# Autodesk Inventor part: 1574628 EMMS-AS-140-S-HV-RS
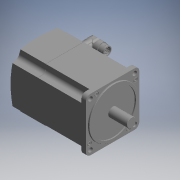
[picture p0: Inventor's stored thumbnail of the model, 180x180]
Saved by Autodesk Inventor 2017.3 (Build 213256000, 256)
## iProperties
Part Number: 1574628 EMMS-AS-140-S-HV-RS
Material: Generic
Catalog Web Link: www.cadenas.de
Description: EMMS-AS-servo motor
Vendor: FESTO
Document SubType Name: Modeling
Designer: partserver
Manufacturer: FESTO
Mass: 9600 g
Surface Area: 1690.04 cm^2
Volume: 3761.7 cm^3
Density: 1 g/cm^3
Appearance: PSOLRGB-175-175-175
Category: PARTsolutions
Company: FESTO
Title: 1574628 EMMS-AS-140-S-HV-RS
Author: Cadenas PARTsolutions
Comments: servo motor
PSOL_IDENT_0: {$CADENAS_DATA\23d-libs\festo\parts\e\emms\emms_as.prj},197 {VTYP=3D},{NB=1574628 EMMS-AS-140-S-HV-R
PSOL_IDENT_1: S},{LINA=1574628 EMMS-AS-140-S-HV-RS},{NN=EMMS-AS},{DATE=30.10.2020 09:47:04},{GEOMDATE=30.10.2020 0
PSOL_IDENT_2: 9:44:16},{VERSION=},{LINEID=5440},{WBVAR=},{WBNUMERIC=}  {NB=1574628 EMMS-AS-140-S-HV-RS},{LINA=1574
PSOL_IDENT_3: 628 EMMS-AS-140-S-HV-RS},{KT=DUMMY},{TNR=1574628},{TYP=EMMS-AS-140-S-HV-RS},{INFO=},{B1=140.500},{B2=
PSOL_IDENT_4: 141.700},{CNSMASSEXACT=9.6000},{VER=9},{VERS=29},{A=209.000},{AA=209},{DP=0},{L=0.0},{L1=0.0},{L2=0.
PSOL_IDENT_5: 0},{L3=0.0},{L4=0.0},{L5=0},{L6=0.0},{L7=0.0},{L8=0.00},{H=0},{H1=0},{H2=0},{D1=0.0},{D2=0.00},{D3=0
PSOL_IDENT_6: .00},{D4=0.0},{D5=0.0},{M=0},{MA=0.000},{M1=0},{M1A=0.000},{EOLDATE=}
NB: 1574628 EMMS-AS-140-S-HV-RS
NN: EMMS-AS
NT: servo motor
NBSYN: $TNR. $TYP.
LINA: 1574628 EMMS-AS-140-S-HV-RS
CATALOG: Festo
TNR: 1574628
TYP: EMMS-AS-140-S-HV-RS
CNSMASSEXACT: 9.6
A: 209
L3: 0
SUPPLIER: FESTO
ARTICLENO: 1574628 EMMS-AS-140-S-HV-RS
BOMINFO: 1574628 EMMS-AS-140-S-HV-RS
CREATOR: CADENAS GmbH
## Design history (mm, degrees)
sketch "Sketch_1"
  geometry: L1 (41, 250)-(41, -250); L2 (-109, -200)-(-109, 200); A1 r 250 centre (41, 0) between (-109, 200) and (-109, -200)
  constraints: 4 end point, 2 point on circle, 1 centre point
revolve "Revolution1" sketch "Sketch_1" stored, may be unused: angle "d0" = 70 deg
sketch "Sketch_2"
  geometry: L1 (-72.5, 72.5)-(-72.5, -72.5); L2 (-72.5, -72.5)-(72.5, -72.5); L3 (72.5, -72.5)-(72.5, 72.5); L4 (72.5, 72.5)-(-72.5, 72.5)
  constraints: 8 end point
extrude "Extrusion1" join sketch "Sketch_2" distance "d1" = 172.4; taper "d2" = 0 deg
sketch "Sketch_9"
  geometry: L1 (-255, -255)-(255, -255); L2 (255, -255)-(255, 255); L3 (255, 255)-(-255, 255); L4 (-255, 255)-(-255, -255); L5 (-70.25, -70.25)-(70.25, -70.25); L6 (70.25, -70.25)-(70.25, 70.25); L7 (70.25, 70.25)-(-70.25, 70.25); L8 (-70.25, 70.25)-(-70.25, -70.25)
  constraints: 16 end point
extrude "Extrusion2" cut sketch "Sketch_9" distance "d3" = 196.8; taper "d4" = 0 deg
sketch "Sketch_6"
  geometry: L1 (-80, -80)-(80, -80); L2 (80, -80)-(80, 80); L3 (80, 80)-(-80, 80); L4 (-80, 80)-(-80, -80); L5 (-78, -49.25)-(-58.25, -49.25); L6 (-49.25, -58.25)-(-49.25, -78); L7 (-49.25, -78)-(49.25, -78); L8 (49.25, -78)-(49.25, -58.25); L9 (58.25, -49.25)-(78, -49.25); L10 (78, -49.25)-(78, 49.25); L11 (78, 49.25)-(58.25, 49.25); L12 (49.25, 58.25)-(49.25, 78); L13 (49.25, 78)-(-49.25, 78); L14 (-49.25, 78)-(-49.25, 58.25); L15 (-58.25, 49.25)-(-78, 49.25); L16 (-78, 49.25)-(-78, -49.25); A1 r 9 centre (-58.25, -58.25) between (-49.25, -58.25) and (-58.25, -49.25); A2 r 9 centre (58.25, -58.25) between (58.25, -49.25) and (49.25, -58.25); A3 r 9 centre (58.25, 58.25) between (49.25, 58.25) and (58.25, 49.25); A4 r 9 centre (-58.25, 58.25) between (-58.25, 49.25) and (-49.25, 58.25)
  constraints: 32 end point, 8 point on circle, 4 centre point
extrude "Extrusion3" cut sketch "Sketch_6" distance "d5" = 199.2; taper "d6" = 0 deg
sketch "Sketch_3"
  geometry: L1 (-80, 80)-(-80, -80); L2 (-80, -80)-(80, -80); L3 (80, -80)-(80, 80); L4 (80, 80)-(-80, 80); L5 (-70.25, 58.25)-(-70.25, -58.25); L6 (-58.25, -70.25)-(58.25, -70.25); L7 (70.25, -58.25)-(70.25, 58.25); L8 (58.25, 70.25)-(-58.25, 70.25); A1 r 12 centre (-58.25, 58.25) between (-58.25, 70.25) and (-70.25, 58.25); A2 r 12 centre (-58.25, -58.25) between (-70.25, -58.25) and (-58.25, -70.25); A3 r 12 centre (58.25, -58.25) between (58.25, -70.25) and (70.25, -58.25); A4 r 12 centre (58.25, 58.25) between (70.25, 58.25) and (58.25, 70.25)
  constraints: 16 end point, 8 point on circle, 4 centre point
extrude "Extrusion4" cut sketch "Sketch_3" distance "d7" = 12.2; taper "d8" = 0 deg
sketch "Sketch_4"
  geometry: L1 (-70.85, 49.85)-(-70.85, -49.85); L2 (-70.85, -49.85)-(-58.85, -49.85); L3 (-49.85, -58.85)-(-49.85, -70.85); L4 (-49.85, -70.85)-(49.85, -70.85); L5 (49.85, -70.85)-(49.85, -58.85); L6 (58.85, -49.85)-(70.85, -49.85); L7 (70.85, -49.85)-(70.85, 49.85); L8 (70.85, 49.85)-(58.85, 49.85); L9 (49.85, 58.85)-(49.85, 70.85); L10 (49.85, 70.85)-(-49.85, 70.85); L11 (-49.85, 70.85)-(-49.85, 58.85); L12 (-58.85, 49.85)-(-70.85, 49.85); A1 r 9 centre (-58.85, -58.85) between (-49.85, -58.85) and (-58.85, -49.85); A2 r 9 centre (58.85, -58.85) between (58.85, -49.85) and (49.85, -58.85); A3 r 9 centre (58.85, 58.85) between (49.85, 58.85) and (58.85, 49.85); A4 r 9 centre (-58.85, 58.85) between (-58.85, 49.85) and (-49.85, 58.85)
  constraints: 24 end point, 8 point on circle, 4 centre point
extrude "Extrusion5" join sketch "Sketch_4" distance "d9" = 45.6; taper "d10" = 0 deg
sketch "Sketch7"
  geometry: 1 further point
hole "Hole1" sketch "Sketch7" at (58.336, 58.336) diameter "d11" = 11.3; stored, may be unused: countersink angle "d15" = 90 deg, drill point angle "d17" = 0 deg; dims "d12" = 6, "d13" = 4, "d14" = 2, "d16" = 12.2
pattern_linear "Rectangular Pattern1" dims "d20" = 116.67262, "d23" = 116.67262
sketch "Sketch_13"
  geometry: L1 (0, 0)-(-50, 0); L2 (-50, 0)-(-50, 11.5); L3 (-50, 11.5)-(-49.5, 12); L4 (-49.5, 12)-(-0.5, 12); L5 (-0.5, 12)-(-0.5, 58); L6 (-0.5, 58)-(-3.5, 58); L7 (-3.5, 58)-(-3.5, 64.5); L8 (-3.5, 64.5)-(-3, 65); L9 (-3, 65)-(0, 65); L10 (0, 65)-(0, 0); L11 (0, 0)-(-50, 0)
  constraints: 22 end point
revolve "Revolution2" sketch "Sketch_13" stored, may be unused: angle "d24" = 360 deg
sketch "Sketch_8"
  geometry: L1 (6, 61)-(-1, 61); L2 (-1, 61)-(-1, 66.5); L3 (-1, 66.5)-(6, 66.5); L4 (6, 66.5)-(6, 66); L5 (6, 66)-(0.6, 66); L6 (0, 65.4)-(0, 61); L7 (0, 61)-(-1, 61); A1 r 0.6 centre (0.6, 65.4) between (0.6, 66) and (0, 65.4)
  constraints: 14 end point, 2 point on circle, 1 centre point
revolve "Revolution3" sketch "Sketch_8" stored, may be unused: angle "d25" = 360 deg
pattern_linear "Rectangular Pattern2" dims "d28" = 105.14038, "d31" = 105.14038
sketch "Sketch_18"
  geometry: L1 (59.557, -40)-(58.113, -42.5); L2 (58.113, -42.5)-(59.557, -45); L3 (59.557, -45)-(62.443, -45); L4 (62.443, -45)-(63.887, -42.5); L5 (63.887, -42.5)-(62.443, -40); L6 (62.443, -40)-(59.557, -40)
  constraints: 12 end point
extrude "Extrusion6" cut sketch "Sketch_18" distance "d32" = 3; taper "d33" = 0 deg
pattern_linear "Rectangular Pattern3" dims "d36" = 105.14038, "d39" = 105.14038
sketch "Sketch_11"
  geometry: L1 (200.5, -61)-(180.5, -61); L2 (180.5, -61)-(180.5, -56.25); L3 (180.5, -56.25)-(200.5, -56.25); L4 (200.5, -56.25)-(200.5, -61); L5 (200.5, -61)-(180.5, -61)
  constraints: 10 end point
revolve "Revolution4" sketch "Sketch_11" stored, may be unused: angle "d40" = 360 deg
sketch "Sketch_50"
  geometry: L1 (200.5, 61)-(180.5, 61); L2 (180.5, 61)-(180.5, 65.75); L3 (180.5, 65.75)-(200.5, 65.75); L4 (200.5, 65.75)-(200.5, 61); L5 (200.5, 61)-(180.5, 61)
  constraints: 10 end point
revolve "Revolution5" sketch "Sketch_50" stored, may be unused: angle "d41" = 360 deg
sketch "Sketch_10"
  geometry: L1 (200.5, 61)-(180.5, 61); L2 (180.5, 61)-(180.5, 65.75); L3 (180.5, 65.75)-(200.5, 65.75); L4 (200.5, 65.75)-(200.5, 61); L5 (200.5, 61)-(180.5, 61)
  constraints: 10 end point
revolve "Revolution6" sketch "Sketch_10" stored, may be unused: angle "d42" = 360 deg
sketch "Sketch_51"
  geometry: L1 (200.5, -61)-(180.5, -61); L2 (180.5, -61)-(180.5, -56.25); L3 (180.5, -56.25)-(200.5, -56.25); L4 (200.5, -56.25)-(200.5, -61); L5 (200.5, -61)-(180.5, -61)
  constraints: 10 end point
revolve "Revolution7" sketch "Sketch_51" stored, may be unused: angle "d43" = 360 deg
sketch "Sketch_12"
  geometry: L1 (195.5, -61)-(180.5, -61); L2 (180.5, -61)-(180.5, -56.75); L3 (180.5, -56.75)-(195.25, -56.75); L4 (195.5, -57)-(195.5, -61); L5 (195.5, -61)-(180.5, -61); A1 r 0.25 centre (195.25, -57) between (195.5, -57) and (195.25, -56.75)
  constraints: 10 end point, 2 point on circle, 1 centre point
revolve "Revolution8" sketch "Sketch_12" stored, may be unused: angle "d44" = 360 deg
sketch "Sketch_14"
  geometry: L1 (195.5, 61)-(175.5, 61); L2 (175.5, 61)-(175.5, 65.25); L3 (175.5, 65.25)-(195.5, 65.25); L4 (195.5, 65.25)-(195.5, 61); L5 (195.5, 61)-(175.5, 61)
  constraints: 10 end point
revolve "Revolution9" sketch "Sketch_14" stored, may be unused: angle "d45" = 360 deg
sketch "Sketch_54"
  geometry: L1 (195.5, 61)-(175.5, 61); L2 (175.5, 61)-(175.5, 65.25); L3 (175.5, 65.25)-(195.5, 65.25); L4 (195.5, 65.25)-(195.5, 61); L5 (195.5, 61)-(175.5, 61)
  constraints: 10 end point
revolve "Revolution10" sketch "Sketch_54" stored, may be unused: angle "d46" = 360 deg
sketch "Sketch_55"
  geometry: L1 (195.5, -61)-(175.5, -61); L2 (175.5, -61)-(175.5, -56.75); L3 (175.5, -56.75)-(195.5, -56.75); L4 (195.5, -56.75)-(195.5, -61); L5 (195.5, -61)-(175.5, -61)
  constraints: 10 end point
revolve "Revolution11" sketch "Sketch_55" stored, may be unused: angle "d47" = 360 deg
sketch "Sketch_15"
  geometry: L1 (-63, 41.345)-(-61, 40.191); L2 (-61, 40.191)-(-59, 41.345); L3 (-59, 41.345)-(-59, 43.655); L4 (-59, 43.655)-(-61, 44.809); L5 (-61, 44.809)-(-63, 43.655); L6 (-63, 43.655)-(-63, 41.345)
  constraints: 12 end point
extrude "Extrusion7" cut sketch "Sketch_15" distance "d48" = 12; taper "d49" = 0 deg
sketch "Sketch_21"
  geometry: L1 (40.5, 59.845)-(42.5, 58.691); L2 (42.5, 58.691)-(44.5, 59.845); L3 (44.5, 59.845)-(44.5, 62.155); L4 (44.5, 62.155)-(42.5, 63.309); L5 (42.5, 63.309)-(40.5, 62.155); L6 (40.5, 62.155)-(40.5, 59.845)
  constraints: 12 end point
extrude "Extrusion8" cut sketch "Sketch_21" distance "d50" = 12; taper "d51" = 0 deg
sketch "Sketch_52"
  geometry: L1 (59, -43.655)-(61, -44.809); L2 (61, -44.809)-(63, -43.655); L3 (63, -43.655)-(63, -41.345); L4 (63, -41.345)-(61, -40.191); L5 (61, -40.191)-(59, -41.345); L6 (59, -41.345)-(59, -43.655)
  constraints: 12 end point
extrude "Extrusion9" cut sketch "Sketch_52" distance "d52" = 12; taper "d53" = 0 deg
sketch "Sketch_53"
  geometry: L1 (-44.5, -62.155)-(-42.5, -63.309); L2 (-42.5, -63.309)-(-40.5, -62.155); L3 (-40.5, -62.155)-(-40.5, -59.845); L4 (-40.5, -59.845)-(-42.5, -58.691); L5 (-42.5, -58.691)-(-44.5, -59.845); L6 (-44.5, -59.845)-(-44.5, -62.155)
  constraints: 12 end point
extrude "Extrusion10" cut sketch "Sketch_53" distance "d54" = 12; taper "d55" = 0 deg
sketch "Sketch_16"
  geometry: L1 (137.9, -22)-(137.9, -45); L2 (137.9, -45)-(138.9, -46); L3 (138.9, -46)-(161.9, -46); L4 (161.9, -46)-(162.9, -45); L5 (162.9, -45)-(162.9, -22); L6 (162.9, -22)-(161.9, -21); L7 (161.9, -21)-(138.9, -21); L8 (138.9, -21)-(137.9, -22)
  constraints: 16 end point
extrude "Extrusion11" join sketch "Sketch_16" distance "d56" = 2.45; taper "d57" = 0 deg
sketch "Sketch_20"
  geometry: L1 (-23.6, 75.65)-(-23.6, 73.3); L2 (-23.6, 73.3)-(-25.85, 73.3); L3 (-25.85, 73.3)-(-25.85, 75.35); L4 (-25.85, 75.35)-(-25.55, 75.65); L5 (-25.55, 75.65)-(-23.6, 75.65); L6 (-23.6, 75.65)-(-23.6, 73.3)
  constraints: 12 end point
revolve "Revolution12" sketch "Sketch_20" stored, may be unused: angle "d58" = 360 deg
pattern_linear "Rectangular Pattern4" dims "d61" = 19.8, "d64" = 19.8
sketch "Sketch_23"
  geometry: L1 (150.4, 94.2)-(150.4, 73.3); L2 (150.4, 73.3)-(143.4, 73.3); L3 (143.4, 73.3)-(143.4, 82.757); L4 (143.4, 82.757)-(143.843, 83.2); L5 (143.843, 83.2)-(145.05, 83.2); L6 (145.05, 83.2)-(145.05, 84.05); L7 (145.05, 84.05)-(144.4, 84.7); L8 (144.4, 84.7)-(144.4, 92.74); L9 (144.4, 92.74)-(144.86, 93.2); L10 (144.86, 93.2)-(145.05, 93.2); L11 (145.05, 93.2)-(145.05, 94.2); L12 (145.05, 94.2)-(150.4, 94.2); L13 (150.4, 94.2)-(150.4, 73.3)
  constraints: 26 end point
revolve "Revolution13" sketch "Sketch_23" stored, may be unused: angle "d65" = 360 deg
thread "Thread1" dims "d66" = 8.04, "d67" = 0
sketch "Sketch_24"
  geometry: L1 (139.5, -24.177)-(140.5, -24.755); L2 (140.5, -24.755)-(141.5, -24.177); L3 (141.5, -24.177)-(141.5, -23.023); L4 (141.5, -23.023)-(140.5, -22.445); L5 (140.5, -22.445)-(139.5, -23.023); L6 (139.5, -23.023)-(139.5, -24.177)
  constraints: 12 end point
extrude "Extrusion12" cut sketch "Sketch_24" distance "d68" = 1.1; taper "d69" = 0 deg
pattern_linear "Rectangular Pattern5" dims "d72" = 19.8, "d75" = 19.8
sketch "Sketch_44"
  geometry: C1 r 4.15 at (0, 0); C2 r 0.4 at (2.743, 0.192); C3 r 0.4 at (1.945, -1.945); C4 r 0.4 at (1.655, 2.196); C5 r 0.4 at (0, 0); C6 r 0.4 at (-0.192, -2.743); C7 r 0.4 at (-0.572, 2.69); C8 r 0.4 at (-2.196, -1.655); C9 r 0.4 at (-2.69, 0.572); 9 further points
  constraints: 9 centre point
extrude "Extrusion13" cut sketch "Sketch_44" distance "d76" = 8.9; taper "d77" = 0 deg
sketch "Sketch28"
  geometry: 1 further point
hole "Hole2" sketch "Sketch28" at (0, 0) diameter "d78" = 8.3; stored, may be unused: countersink angle "d82" = 90 deg, drill point angle "d84" = 0 deg; dims "d79" = 6, "d80" = 4, "d81" = 2, "d83" = 1.95
sketch "Sketch_46"
  geometry: L1 (-3.328, 2.479)-(-2.927, 2.079); L2 (-2.079, 2.927)-(-2.479, 3.328); A1 r 0.6 centre (-2.503, 2.503) between (-2.927, 2.079) and (-2.079, 2.927); A2 r 4.15 centre (0, 0) between (-2.479, 3.328) and (-3.328, 2.479)
  constraints: 4 end point, 4 point on circle, 2 centre point
extrude "Extrusion14" join sketch "Sketch_46" distance "d85" = 8.9; taper "d86" = 0 deg
sketch "Sketch_47"
  geometry: C1 r 4.15 at (0, 0); 1 further point
  constraints: 1 centre point
extrude "Extrusion15" cut sketch "Sketch_47" distance "d87" = 0.5; taper "d88" = 0 deg
sketch "Sketch_26"
  geometry: L1 (140.05, 20.65)-(160.75, 20.65); L2 (163.25, 23.15)-(163.25, 43.85); L3 (160.75, 46.35)-(140.05, 46.35); L4 (137.55, 43.85)-(137.55, 23.15); A1 r 2.5 centre (140.05, 23.15) between (137.55, 23.15) and (140.05, 20.65); A2 r 2.5 centre (160.75, 23.15) between (160.75, 20.65) and (163.25, 23.15); A3 r 2.5 centre (160.75, 43.85) between (163.25, 43.85) and (160.75, 46.35); A4 r 2.5 centre (140.05, 43.85) between (140.05, 46.35) and (137.55, 43.85)
  constraints: 8 end point, 8 point on circle, 4 centre point
extrude "Extrusion16" join sketch "Sketch_26" distance "d89" = 2.6; taper "d90" = 0 deg
sketch "Sketch_30"
  geometry: L1 (23.6, 75.6)-(23.6, 73.25); L2 (23.6, 73.25)-(21.35, 73.25); L3 (21.35, 73.25)-(21.35, 75.35); L4 (21.35, 75.35)-(21.6, 75.6); L5 (21.6, 75.6)-(23.6, 75.6); L6 (23.6, 75.6)-(23.6, 73.25)
  constraints: 12 end point
revolve "Revolution14" sketch "Sketch_30" stored, may be unused: angle "d91" = 360 deg
pattern_linear "Rectangular Pattern6" dims "d94" = 19.8, "d97" = 19.8
sketch "Sketch_31"
  geometry: L1 (139.5, 23.023)-(140.5, 22.445); L2 (140.5, 22.445)-(141.5, 23.023); L3 (141.5, 23.023)-(141.5, 24.177); L4 (141.5, 24.177)-(140.5, 24.755); L5 (140.5, 24.755)-(139.5, 24.177); L6 (139.5, 24.177)-(139.5, 23.023)
  constraints: 12 end point
extrude "Extrusion17" cut sketch "Sketch_31" distance "d98" = 1.1; taper "d99" = 0 deg
pattern_linear "Rectangular Pattern7" dims "d102" = 19.8, "d105" = 19.8
sketch "Sketch_29"
  geometry: L1 (150.4, 100.1)-(150.4, 73.25); L2 (150.4, 73.25)-(137.9, 73.25); L3 (137.9, 73.25)-(137.9, 81.25); L4 (137.9, 81.25)-(138.4, 81.25); L5 (138.4, 81.25)-(138.4, 100.1); L6 (138.4, 100.1)-(150.4, 100.1); L7 (150.4, 100.1)-(150.4, 73.25)
  constraints: 14 end point
revolve "Revolution15" sketch "Sketch_29" stored, may be unused: angle "d106" = 360 deg
sketch "Sketch_60"
  geometry: L1 (23.6, 81.25)-(23.6, 99.25); L2 (23.6, 99.25)-(26.6, 99.25); L3 (26.6, 99.25)-(26.6, 81.25); L4 (26.6, 81.25)-(23.6, 81.25); L5 (23.6, 81.25)-(23.6, 99.25)
  constraints: 10 end point
revolve "Revolution16" sketch "Sketch_60" stored, may be unused: angle "d107" = 360 deg
pattern_linear "Rectangular Pattern8" dims "d110" = 19.8, "d113" = 19.8
sketch "Sketch_27"
  geometry: L1 (163.25, 97.7)-(111.39, 97.7); L2 (111.39, 97.7)-(111.39, 108.7); L3 (111.39, 108.7)-(116.39, 108.7); L4 (116.39, 108.7)-(116.39, 109.2); L5 (116.39, 109.2)-(123.39, 109.2); L6 (123.39, 109.2)-(123.39, 108.7); L7 (123.39, 108.7)-(125.39, 108.7); L8 (125.39, 108.7)-(125.39, 110.45); L9 (125.39, 110.45)-(163.25, 110.45); L10 (163.25, 110.45)-(163.25, 97.7); L11 (163.25, 97.7)-(111.39, 97.7)
  constraints: 22 end point
revolve "Revolution17" sketch "Sketch_27" stored, may be unused: angle "d114" = 360 deg
sketch "Sketch_33"
  geometry: L1 (28.55, 110.25)-(28.55, 97.7); L2 (28.55, 97.7)-(38.45, 97.7); L3 (38.45, 97.7)-(38.45, 110.25); L4 (38.45, 110.25)-(28.55, 110.25)
  constraints: 8 end point
extrude "Extrusion18" join sketch "Sketch_33" distance "d115" = 37.86; taper "d116" = 0 deg
sketch "Sketch_36"
  geometry: L1 (28.55, 112.25)-(28.55, 110.25); L2 (28.55, 110.25)-(38.45, 110.25); L3 (38.45, 110.25)-(38.45, 112.25); L4 (38.45, 112.25)-(28.55, 112.25)
  constraints: 8 end point
extrude "Extrusion19" cut sketch "Sketch_36" distance "d117" = 37.86; taper "d118" = 0 deg
sketch "Sketch_34"
  geometry: L1 (144.9, 47.5)-(150.5, 46.25); L2 (150.5, 20.75)-(144.9, 19.5); L3 (139.9, 14.5)-(169.9, 14.5); L4 (169.9, 14.5)-(169.9, 52.5); L5 (169.9, 52.5)-(139.9, 52.5); A1 r 5 centre (139.9, 47.5) between (139.9, 52.5) and (144.9, 47.5); A2 r 12.75 centre (150.5, 33.5) between (150.5, 20.75) and (150.5, 46.25); A3 r 5 centre (139.9, 19.5) between (144.9, 19.5) and (139.9, 14.5)
  constraints: 10 end point, 6 point on circle, 3 centre point
extrude "Extrusion20" cut sketch "Sketch_34" distance "d119" = 27; taper "d120" = 0 deg
sketch "Sketch_35"
  geometry: L1 (31.6, 110.45)-(31.6, 110.25); L2 (31.6, 110.25)-(35.4, 110.25); L3 (35.4, 110.25)-(35.4, 110.45); L4 (35.4, 110.45)-(31.6, 110.45)
  constraints: 8 end point
extrude "Extrusion21" join sketch "Sketch_35" distance "d121" = 3; taper "d122" = 0 deg
sketch "Sketch_48"
  geometry: C1 r 9 at (0, 0); C2 r 0.5 at (5.196, 3); C3 r 1 at (5.196, -3); C4 r 0.5 at (2.052, 5.638); C5 r 1 at (0, 0); C6 r 1 at (0, -6); C7 r 0.5 at (-2.052, 5.638); C8 r 0.5 at (-5.196, 3); C9 r 1 at (-5.196, -3); 9 further points
  constraints: 9 centre point
extrude "Extrusion22" cut sketch "Sketch_48" distance "d123" = 11.5; taper "d124" = 0 deg
sketch "Sketch42"
  geometry: 1 further point
hole "Hole3" sketch "Sketch42" at (0, 0) diameter "d125" = 18; stored, may be unused: countersink angle "d129" = 90 deg, drill point angle "d131" = 0 deg; dims "d126" = 6, "d127" = 4, "d128" = 2, "d130" = 1
sketch "Sketch_58"
  geometry: L1 (23.6, 73.3)-(23.6, 81.3); L2 (23.6, 81.3)-(26.1, 81.3); L3 (26.1, 81.3)-(26.1, 73.3); L4 (26.1, 73.3)-(25.85, 73.3); L5 (25.85, 73.3)-(25.85, 75.353); L6 (25.85, 75.353)-(25.603, 75.6); L7 (25.603, 75.6)-(23.6, 75.6); L8 (23.6, 75.6)-(23.6, 81.3)
  constraints: 16 end point
revolve "Revolution18" sketch "Sketch_58" stored, may be unused: angle "d132" = 360 deg
pattern_linear "Rectangular Pattern9" dims "d135" = 19.8, "d138" = 19.8
node "ANBAU_XY"
node "ANBAU_YZ"
node "ANBAU_ZX"
node "ANBAU_X"
node "ANBAU_Y"
node "ANBAU_Z"
node "ANBAU_Center"
node "ENCODERLEITUNG_XY"
node "ENCODERLEITUNG_YZ"
node "ENCODERLEITUNG_ZX"
node "ENCODERLEITUNG_X"
node "ENCODERLEITUNG_Y"
node "ENCODERLEITUNG_Z"
node "ENCODERLEITUNG_Center"
node "HGOSCREW_1_XY"
node "HGOSCREW_1_YZ"
node "HGOSCREW_1_ZX"
node "HGOSCREW_1_X"
node "HGOSCREW_1_Y"
node "HGOSCREW_1_Z"
node "HGOSCREW_1_Center"
node "HGOSCREW_2_XY"
node "HGOSCREW_2_YZ"
node "HGOSCREW_2_ZX"
node "HGOSCREW_2_X"
node "HGOSCREW_2_Y"
node "HGOSCREW_2_Z"
node "HGOSCREW_2_Center"
node "HGOSCREW_3_XY"
node "HGOSCREW_3_YZ"
node "HGOSCREW_3_ZX"
node "HGOSCREW_3_X"
node "HGOSCREW_3_Y"
node "HGOSCREW_3_Z"
node "HGOSCREW_3_Center"
node "HGOSCREW_4_XY"
node "HGOSCREW_4_YZ"
node "HGOSCREW_4_ZX"
node "HGOSCREW_4_X"
node "HGOSCREW_4_Y"
node "HGOSCREW_4_Z"
node "HGOSCREW_4_Center"
node "MOTORLEITUNG_XY"
node "MOTORLEITUNG_YZ"
node "MOTORLEITUNG_ZX"
node "MOTORLEITUNG_X"
node "MOTORLEITUNG_Y"
node "MOTORLEITUNG_Z"
node "MOTORLEITUNG_Center"
body "Solid1"
other parameters: "d139" = 0, "d140" = 0, "d141" = 0, "d142" = 0, "d143" = 0, "d144" = 0
